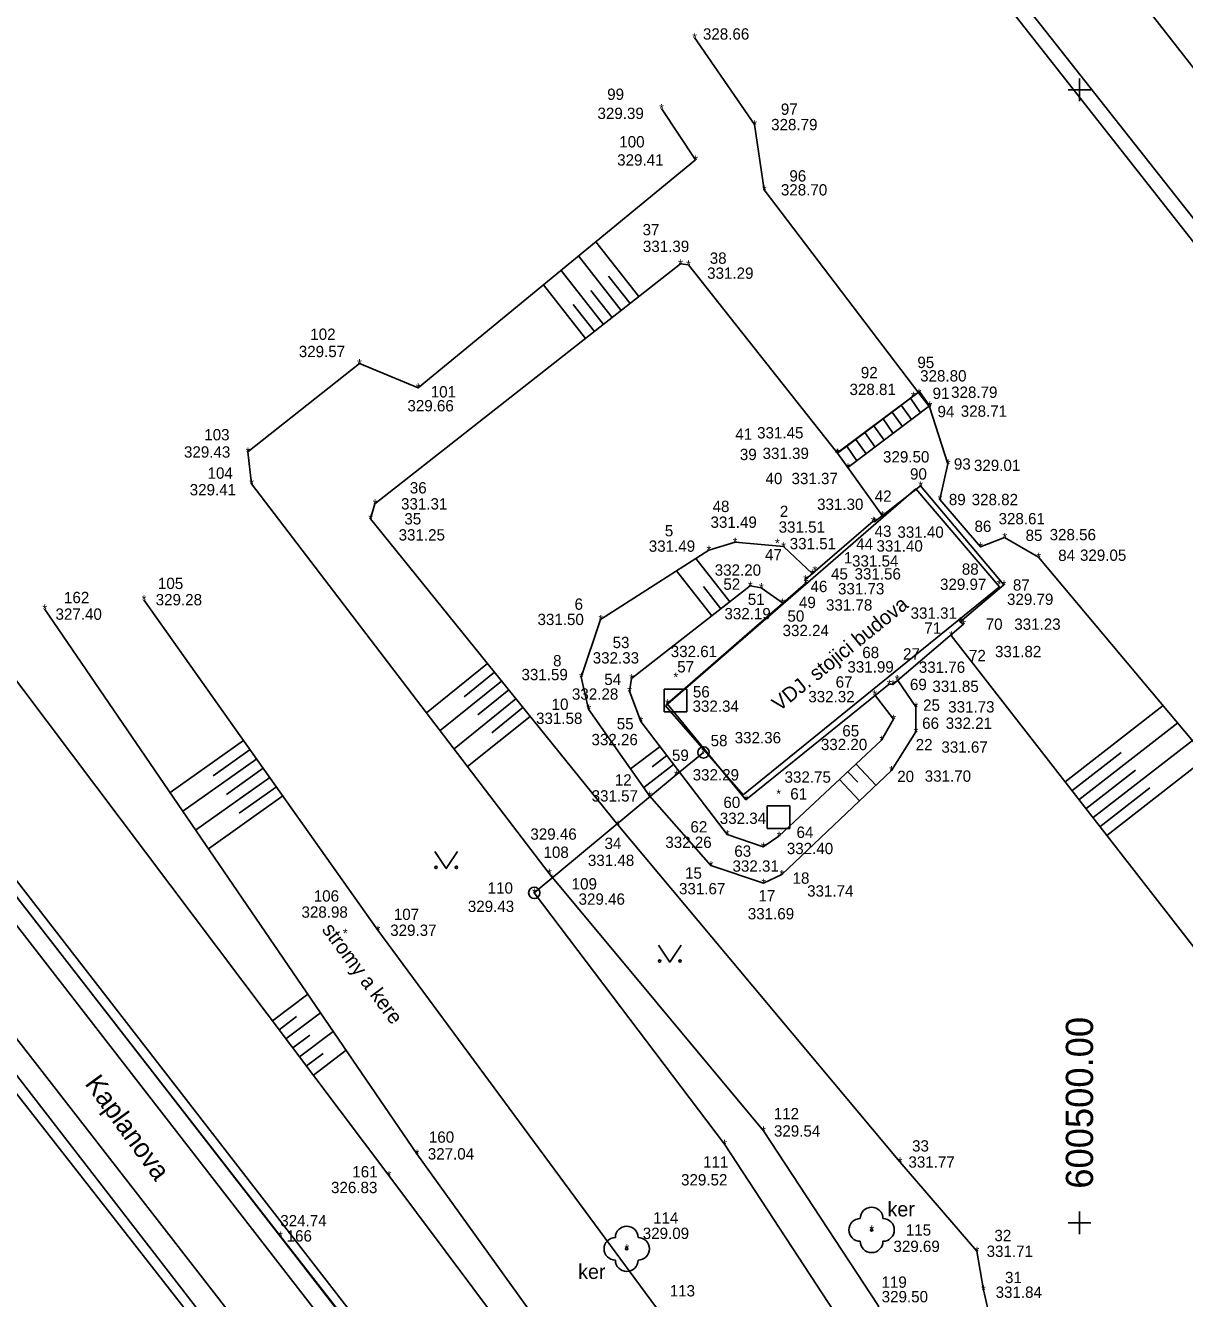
# Model space of a CAD drawing. Extents: x -600587 to -600377, y -1159886 to -1159708.
# Drawn here: x -600546.5 to -600495.4, y -1159803.3 to -1159747.2 of the extents above; entities that cross this region are included whole.
import ezdxf

# ---------------------------------------------------------------- set-up
doc = ezdxf.new("R2010")
doc.units = 0
for name, color, linetype in [('Hranice parcel', 7, 'Continuous'), ('Pop  PČ popisy', 7, 'Continuous'), ('Vnitřní kresba', 7, 'Continuous'), ('Vrstva 11', 7, 'Continuous'), ('Vrstva 13', 7, 'Continuous'), ('Vrstva 20', 7, 'Continuous'), ('Vrstva 22', 7, 'Continuous'), ('Vrstva 34', 7, 'Continuous'), ('Vrstva 36', 7, 'Continuous'), ('Vrstva 40', 7, 'Continuous'), ('Vrstva 58', 7, 'Continuous'), ('Vrstva 59', 7, 'Continuous'), ('Vrstva 60', 7, 'Continuous'), ('Vrstva 62', 7, 'Continuous'), ('Vrstva 63', 7, 'Continuous'), ('Vrstva 7', 7, 'Continuous'), ('Vrstva 8', 7, 'Continuous')]:
    doc.layers.add(name, color=color, linetype=linetype)

msp = doc.modelspace()

# ---------------------------------------------------------------- linework, layer by layer
at = {"layer": 'Hranice parcel'}
for points in [[(-600530.91, -1159710.13), (-600493.42, -1159757.63), (-600491.23, -1159760.48), (-600448.05, -1159816.59)], [(-600488.61, -1159847.98), (-600490.62, -1159848.62), (-600491.99, -1159848.82), (-600493.39, -1159848.77), (-600494.93, -1159848.62), (-600496.36, -1159848.13), (-600500.23, -1159845.75), (-600572.32, -1159752.89), (-600572.98, -1159751.48), (-600573.33, -1159750.24), (-600573.44, -1159748.95), (-600573.44, -1159747.6), (-600573.32, -1159746.25), (-600573.13, -1159744.93), (-600572.66, -1159743.72), (-600571.05, -1159741.4), (-600570.22, -1159740.33), (-600564.67, -1159736.09)], [(-600524.43, -1159822.45), (-600525.46, -1159821.09), (-600527.36, -1159818.8), (-600536.8, -1159806.55), (-600551.99, -1159786.94)]]:
    msp.add_lwpolyline(points, dxfattribs=at)
at = {"layer": 'Vnitřní kresba'}
for p, q in [((-600525.36, -1159709.98), (-600494.19, -1159750.03)), ((-600531.09, -1159710.8), (-600493.91, -1159758.06)), ((-600580.267, -1159748.971), (-600497.15, -1159855.9)), ((-600499.96, -1159845.44), (-600571.89, -1159752.7)), ((-600503.93, -1159842.26), (-600567.61, -1159760.2)), ((-600518.27, -1159777.18), (-600507.22, -1159767.61)), ((-600507.22, -1159767.61), (-600503.52, -1159771.93)), ((-600503.52, -1159771.93), (-600514.84, -1159781.11)), ((-600514.84, -1159781.11), (-600518.27, -1159777.18)), ((-600537.12, -1159806.8), (-600552.47, -1159787.22))]:
    msp.add_line(p, q, dxfattribs=at)
at = {"layer": 'Vrstva 11'}
for p, q in [((-600518.45, -1159750.82), (-600516.94, -1159753.09)), ((-600519.44, -1159759.12), (-600521.34, -1159756.7)), ((-600520.22, -1159759.73), (-600522.11, -1159757.33)), ((-600521.01, -1159760.35), (-600522.88, -1159757.97)), ((-600519.83, -1159759.42), (-600520.78, -1159758.22)), ((-600521.8, -1159760.97), (-600523.65, -1159758.6)), ((-600520.62, -1159760.04), (-600521.56, -1159758.85)), ((-600521.4, -1159760.66), (-600522.34, -1159759.47)), ((-600507.412, -1159764.554), (-600507.862, -1159763.914)), ((-600507.011, -1159764.252), (-600507.461, -1159763.612)), ((-600508.214, -1159765.159), (-600508.664, -1159764.519)), ((-600507.813, -1159764.857), (-600508.263, -1159764.217)), ((-600509.017, -1159765.763), (-600509.467, -1159765.123)), ((-600508.616, -1159765.461), (-600509.066, -1159764.821)), ((-600509.418, -1159766.066), (-600509.868, -1159765.426)), ((-600509.819, -1159766.368), (-600510.269, -1159765.728)), ((-600515.43, -1159772.59), (-600516.93, -1159770.68)), ((-600516.22, -1159773.21), (-600517.78, -1159771.22)), ((-600515.83, -1159772.9), (-600516.59, -1159771.92)), ((-600526.13, -1159775.31), (-600528.82, -1159777.49)), ((-600525.82, -1159775.7), (-600527.16, -1159776.79)), ((-600525.5, -1159776.09), (-600528.21, -1159778.28)), ((-600524.87, -1159776.87), (-600527.6, -1159779.08)), ((-600525.19, -1159776.48), (-600526.55, -1159777.58)), ((-600524.56, -1159777.26), (-600525.93, -1159778.37)), ((-600500.63, -1159780.54), (-600496.3, -1159777.17)), ((-600524.24, -1159777.65), (-600527, -1159779.87)), ((-600500.02, -1159781.33), (-600495.66, -1159777.94)), ((-600536.89, -1159778.72), (-600540.13, -1159781.01)), ((-600536.6, -1159779.12), (-600538.23, -1159780.28)), ((-600518.51, -1159778.98), (-600519.81, -1159779.97)), ((-600499.4, -1159782.12), (-600495.01, -1159778.71)), ((-600536.31, -1159779.53), (-600539.57, -1159781.84)), ((-600518.21, -1159779.38), (-600518.86, -1159779.88)), ((-600500.33, -1159780.94), (-600498.15, -1159779.25)), ((-600498.79, -1159782.91), (-600494.37, -1159779.47)), ((-600536.02, -1159779.94), (-600537.65, -1159781.1)), ((-600517.91, -1159779.77), (-600519.23, -1159780.79)), ((-600510.22, -1159780.1), (-600509.78, -1159780.56)), ((-600509.86, -1159779.76), (-600508.98, -1159780.69)), ((-600499.71, -1159781.73), (-600497.52, -1159780.03)), ((-600535.73, -1159780.35), (-600539.01, -1159782.67)), ((-600535.44, -1159780.76), (-600537.08, -1159781.92)), ((-600510.59, -1159780.44), (-600509.71, -1159781.38)), ((-600499.1, -1159782.52), (-600496.89, -1159780.8)), ((-600535.16, -1159781.16), (-600538.44, -1159783.49)), ((-600535.62, -1159791.09), (-600534.06, -1159789.91)), ((-600535.32, -1159791.49), (-600534.55, -1159790.9)), ((-600535.02, -1159791.88), (-600533.49, -1159790.74)), ((-600534.72, -1159792.28), (-600533.96, -1159791.72)), ((-600534.42, -1159792.68), (-600532.93, -1159791.56)), ((-600534.11, -1159793.08), (-600533.38, -1159792.53)), ((-600533.81, -1159793.48), (-600532.36, -1159792.39))]:
    msp.add_line(p, q, dxfattribs=at)
for points in [[(-600505.8, -1159766.51), (-600506.62, -1159763.99), (-600507.09, -1159763.39), (-600513.91, -1159754.41), (-600514.34, -1159751.53), (-600516.99, -1159747.69)], [(-600516.94, -1159753.09), (-600529.19, -1159763.15), (-600531.78, -1159762.08), (-600536.7, -1159765.98), (-600536.54, -1159767.38), (-600523.4, -1159784.58), (-600513.95, -1159795.95), (-600508.88, -1159803.66), (-600507.89, -1159806.61), (-600497.07, -1159821.79)], [(-600484.2, -1159818.25), (-600488.9, -1159822.049), (-600490.752, -1159822.336), (-600491.864, -1159821.583), (-600494.57, -1159818.11), (-600499.67, -1159810.97), (-600503.93, -1159804.31), (-600504.24, -1159802.96), (-600504.53, -1159801.26), (-600507.92, -1159797.32), (-600520.37, -1159782.44), (-600531.29, -1159768.93), (-600531.09, -1159768.27), (-600517.61, -1159757.68), (-600517.26, -1159757.72), (-600510.67, -1159766.03), (-600510.22, -1159766.67), (-600508.71, -1159768.78)], [(-600510.67, -1159766.03), (-600507.06, -1159763.31), (-600506.61, -1159763.95)], [(-600510.67, -1159766.03), (-600510.22, -1159766.67), (-600506.61, -1159763.95)], [(-600502.72, -1159834.41), (-600509.56, -1159825.58), (-600519.31, -1159812.85), (-600530.48, -1159797.91), (-600554.16, -1159766.46)], [(-600473.743, -1159793.926), (-600480.83, -1159785.76), (-600491.06, -1159783.42), (-600501.8, -1159770.62), (-600503.3, -1159769.75), (-600504.37, -1159770.17), (-600506.16, -1159768.08), (-600505.8, -1159766.51)], [(-600511.78, -1159771.36), (-600513.06, -1159770.16), (-600515.2, -1159769.96), (-600516.36, -1159770.31), (-600521.13, -1159773.37), (-600521.99, -1159775.92), (-600521.66, -1159777.33), (-600518.97, -1159781.16), (-600516.27, -1159784.24), (-600513.94, -1159785.01), (-600513.14, -1159784.63), (-600508.3, -1159780.04), (-600507.22, -1159778.34), (-600507.22, -1159777.23), (-600508.05, -1159776.03)], [(-600513.1, -1159772.64), (-600514.04, -1159771.97), (-600514.53, -1159771.89), (-600519.77, -1159775.98), (-600519.86, -1159776.54), (-600519.36, -1159777.87), (-600515.55, -1159782.86), (-600513.96, -1159783.41), (-600513.26, -1159782.94), (-600508.73, -1159778.7), (-600508.2, -1159777.77), (-600509.04, -1159776.69)], [(-600508.65, -1159825.2), (-600518.33, -1159812.15), (-600529.24, -1159796.96), (-600545.67, -1159772.91)], [(-600541.29, -1159772.5), (-600530.96, -1159787.09), (-600518.71, -1159803.7), (-600511.21, -1159813.31), (-600502.87, -1159824.07)], [(-600505.66, -1159774.08), (-600492.78, -1159790.64), (-600491.93, -1159791.2), (-600487.96, -1159791.96), (-600485.28, -1159791.6), (-600484.47, -1159791.86), (-600480.26, -1159798.5)]]:
    msp.add_lwpolyline(points, dxfattribs=at)
at = {"layer": 'Vrstva 13'}
msp.add_lwpolyline([(-600497.65, -1159824.35), (-600503.84, -1159814.83), (-600509.44, -1159806.04), (-600515.67, -1159796.54), (-600524.06, -1159785.44), (-600517.8, -1159780.23), (-600516.59, -1159779.24)], dxfattribs=at)
at = {"layer": 'Vrstva 20'}
msp.add_lwpolyline([(-600509.05, -1159769.06), (-600509.1, -1159769.04), (-600512.09, -1159771.61), (-600512.08, -1159771.77), (-600518.19, -1159777.09), (-600514.72, -1159781.33), (-600508.4, -1159776.23), (-600508.23, -1159776.24), (-600505.12, -1159773.58), (-600505.27, -1159773.48), (-600503.34, -1159771.85), (-600507.01, -1159767.47)], close=True, dxfattribs=at)
at = {"layer": 'Vrstva 22'}
for centre in [(-600509.17, -1159800.32), (-600519.98, -1159801.15)]:
    msp.add_circle(centre, 0.05, dxfattribs=at)
for centre, start, end in [((-600509.17, -1159799.82), 0, 180), ((-600509.67, -1159800.32), 90, 270), ((-600508.67, -1159800.32), 270, 90), ((-600519.98, -1159800.65), 0, 180), ((-600520.48, -1159801.15), 90, 270), ((-600519.48, -1159801.15), 270, 90), ((-600509.17, -1159800.82), 180, 0), ((-600519.98, -1159801.65), 180, 0)]:
    msp.add_arc(centre, 0.5, start, end, dxfattribs=at)
at = {"layer": 'Vrstva 34'}
for p, q in [((-600517.32, -1159776.45), (-600518.32, -1159776.45)), ((-600518.32, -1159776.45), (-600518.32, -1159777.45)), ((-600517.32, -1159777.45), (-600517.32, -1159776.45)), ((-600518.32, -1159777.45), (-600517.32, -1159777.45)), ((-600512.78, -1159781.6), (-600513.78, -1159781.6)), ((-600513.78, -1159781.6), (-600513.78, -1159782.6)), ((-600512.78, -1159782.6), (-600512.78, -1159781.6)), ((-600513.78, -1159782.6), (-600512.78, -1159782.6))]:
    msp.add_line(p, q, dxfattribs=at)
at = {"layer": 'Vrstva 36'}
for points in [[(-600528.446, -1159783.616), (-600527.946, -1159784.366), (-600527.446, -1159783.616)], [(-600518.577, -1159787.749), (-600518.077, -1159788.499), (-600517.577, -1159787.749)]]:
    msp.add_lwpolyline(points, dxfattribs=at)
for centre in [(-600528.397, -1159784.316), (-600527.497, -1159784.316), (-600518.527, -1159788.449), (-600517.628, -1159788.449)]:
    msp.add_circle(centre, 0.05, dxfattribs=at)
at = {"layer": 'Vrstva 63'}
for p, q in [((-600500, -1159749.5), (-600500, -1159750.5)), ((-600500.5, -1159750), (-600499.5, -1159750)), ((-600500, -1159799.5), (-600500, -1159800.5)), ((-600500.5, -1159800), (-600499.5, -1159800))]:
    msp.add_line(p, q, dxfattribs=at)
at = {"layer": 'Vrstva 7'}
msp.add_lwpolyline([(-600566.21, -1159760.89), (-600549.54, -1159782.24), (-600535.27, -1159800.58), (-600519.17, -1159821.21), (-600501, -1159844.58)], dxfattribs=at)
at = {"layer": 'Vrstva 8'}
msp.add_lwpolyline([(-600510.71, -1159766.04), (-600507.34, -1159763.52)], dxfattribs=at)
for centre, radius in [((-600516.591, -1159779.24), 0.25), ((-600516.591, -1159779.24), 0.0005), ((-600524.061, -1159785.44), 0.25), ((-600524.061, -1159785.44), 0.0005)]:
    msp.add_circle(centre, radius, dxfattribs=at)

# ---------------------------------------------------------------- texts
at = {"layer": 'Pop  PČ popisy'}
msp.add_text('Kaplanova', height=0.85, rotation=306, dxfattribs=at).set_placement((-600543.924, -1159793.865))
at = {"layer": 'Vrstva 40'}
for s, rotation, p in [('VDJ. stojici budova', 38.9022, (-600513.248, -1159777.453)), ('stromy a kere', 306.4091, (-600533.463, -1159787.069))]:
    msp.add_text(s, height=0.65, rotation=rotation, dxfattribs=at).set_placement(p)
for p in [(-600508.471, -1159799.724), (-600522.124, -1159802.483)]:
    msp.add_text('ker', height=0.65, dxfattribs=at).set_placement(p)
at = {"layer": 'Vrstva 58'}
for s, p in [('328.66', (-600516.616, -1159747.78)), ('329.39', (-600521.27, -1159751.284)), ('328.79', (-600513.605, -1159751.78)), ('329.41', (-600520.401, -1159753.34)), ('328.70', (-600513.175, -1159754.66)), ('331.39', (-600519.267, -1159757.153)), ('331.29', (-600516.431, -1159758.338)), ('329.57', (-600534.453, -1159761.795)), ('328.80', (-600507.029, -1159762.87)), ('328.81', (-600510.146, -1159763.468)), ('328.79', (-600505.663, -1159763.593)), ('329.66', (-600529.658, -1159764.189)), ('328.71', (-600505.237, -1159764.427)), ('331.45', (-600514.225, -1159765.384)), ('329.43', (-600539.52, -1159766.23)), ('331.39', (-600513.984, -1159766.29)), ('329.50', (-600508.667, -1159766.444)), ('329.01', (-600504.655, -1159766.821)), ('331.37', (-600512.706, -1159767.401)), ('329.41', (-600539.266, -1159767.897)), ('328.82', (-600504.755, -1159768.33)), ('331.31', (-600529.941, -1159768.52)), ('331.30', (-600511.577, -1159768.539)), ('331.49', (-600516.282, -1159769.329)), ('331.51', (-600513.275, -1159769.544)), ('328.61', (-600503.568, -1159769.174)), ('331.25', (-600530.047, -1159769.889)), ('331.40', (-600508.032, -1159769.767)), ('328.56', (-600501.315, -1159769.878)), ('331.49', (-600519.006, -1159770.386)), ('331.51', (-600512.785, -1159770.275)), ('331.40', (-600508.957, -1159770.378)), ('331.54', (-600510.034, -1159771.04)), ('329.05', (-600499.975, -1159770.786)), ('332.20', (-600516.095, -1159771.442)), ('331.56', (-600509.924, -1159771.61)), ('331.73', (-600510.654, -1159772.267)), ('329.97', (-600506.152, -1159772.07)), ('329.28', (-600540.769, -1159772.75)), ('329.79', (-600503.195, -1159772.732)), ('327.40', (-600545.189, -1159773.387)), ('332.19', (-600515.667, -1159773.367)), ('331.78', (-600511.185, -1159772.983)), ('331.31', (-600507.451, -1159773.341)), ('331.50', (-600523.917, -1159773.62)), ('331.23', (-600502.875, -1159773.83)), ('332.24', (-600513.1, -1159774.109)), ('332.61', (-600518.036, -1159775.035)), ('331.82', (-600503.728, -1159775.04)), ('332.33', (-600521.48, -1159775.318)), ('331.99', (-600510.24, -1159775.716)), ('331.76', (-600507.088, -1159775.73)), ('331.59', (-600524.624, -1159776.055)), ('331.85', (-600506.489, -1159776.572)), ('332.28', (-600522.397, -1159776.915)), ('332.32', (-600511.965, -1159777.03)), ('331.58', (-600523.981, -1159777.985)), ('332.34', (-600517.074, -1159777.45)), ('331.73', (-600505.792, -1159777.48)), ('332.21', (-600505.902, -1159778.203)), ('332.26', (-600521.534, -1159778.925)), ('332.36', (-600515.214, -1159778.84)), ('332.20', (-600511.41, -1159779.14)), ('331.67', (-600506.09, -1159779.255)), ('332.29', (-600517.069, -1159780.48)), ('332.75', (-600513.013, -1159780.579)), ('331.70', (-600506.826, -1159780.535)), ('331.57', (-600521.528, -1159781.41)), ('332.34', (-600515.873, -1159782.398)), ('329.46', (-600524.232, -1159783.095)), ('332.26', (-600518.276, -1159783.458)), ('332.40', (-600512.913, -1159783.731)), ('331.48', (-600521.693, -1159784.255)), ('332.31', (-600515.31, -1159784.507)), ('331.67', (-600517.673, -1159785.506)), ('331.74', (-600512.017, -1159785.605)), ('329.43', (-600526.992, -1159786.286)), ('329.46', (-600522.104, -1159785.965)), ('328.98', (-600534.334, -1159786.538)), ('331.69', (-600514.635, -1159786.611)), ('329.37', (-600530.418, -1159787.34)), ('329.54', (-600513.482, -1159796.2)), ('327.04', (-600528.759, -1159797.21)), ('331.77', (-600507.546, -1159797.57)), ('326.83', (-600533.03, -1159798.695)), ('329.52', (-600517.581, -1159798.355)), ('324.74', (-600535.27, -1159800.161)), ('329.09', (-600519.272, -1159800.718)), ('329.69', (-600508.208, -1159801.292)), ('331.71', (-600504.095, -1159801.51)), ('329.50', (-600508.727, -1159803.513)), ('331.84', (-600503.698, -1159803.317))]:
    msp.add_text(s, height=0.5, dxfattribs=at).set_placement(p)
at = {"layer": 'Vrstva 59'}
for s, p in [('99', (-600520.842, -1159750.441)), ('97', (-600513.177, -1159751.098)), ('100', (-600520.308, -1159752.538)), ('96', (-600512.801, -1159754.045)), ('37', (-600519.28, -1159756.417)), ('38', (-600516.315, -1159757.676)), ('102', (-600533.946, -1159761.033)), ('92', (-600509.648, -1159762.726)), ('95', (-600507.151, -1159762.277)), ('101', (-600528.629, -1159763.574)), ('91', (-600506.479, -1159763.641)), ('94', (-600506.263, -1159764.446)), ('103', (-600538.624, -1159765.468)), ('41', (-600515.187, -1159765.443)), ('39', (-600514.986, -1159766.339)), ('93', (-600505.54, -1159766.76)), ('104', (-600538.478, -1159767.162)), ('90', (-600507.476, -1159767.2)), ('36', (-600529.553, -1159767.811)), ('40', (-600513.855, -1159767.401)), ('42', (-600509.034, -1159768.179)), ('89', (-600505.763, -1159768.33)), ('48', (-600516.189, -1159768.633)), ('2', (-600513.222, -1159768.85)), ('35', (-600529.793, -1159769.18)), ('86', (-600504.63, -1159769.511)), ('5', (-600518.298, -1159769.703)), ('43', (-600509.039, -1159769.728)), ('85', (-600502.376, -1159769.908)), ('44', (-600509.852, -1159770.287)), ('47', (-600513.876, -1159770.768)), ('1', (-600510.397, -1159770.902)), ('84', (-600500.937, -1159770.794)), ('45', (-600510.963, -1159771.61)), ('88', (-600505.19, -1159771.4)), ('105', (-600540.668, -1159772.03)), ('52', (-600515.714, -1159772.064)), ('46', (-600511.869, -1159772.166)), ('87', (-600502.935, -1159772.1)), ('162', (-600544.815, -1159772.654)), ('51', (-600514.636, -1159772.732)), ('49', (-600512.378, -1159772.871)), ('6', (-600522.282, -1159772.947)), ('50', (-600512.886, -1159773.471)), ('71', (-600506.847, -1159774.006)), ('70', (-600504.135, -1159773.83)), ('53', (-600520.602, -1159774.638)), ('68', (-600509.583, -1159775.081)), ('27', (-600507.783, -1159775.143)), ('8', (-600523.229, -1159775.444)), ('57', (-600517.751, -1159775.711)), ('72', (-600504.873, -1159775.216)), ('54', (-600520.969, -1159776.265)), ('56', (-600517.059, -1159776.816)), ('67', (-600510.758, -1159776.381)), ('69', (-600507.48, -1159776.49)), ('10', (-600523.294, -1159777.366)), ('25', (-600506.899, -1159777.404)), ('55', (-600520.419, -1159778.222)), ('65', (-600510.463, -1159778.537)), ('66', (-600506.94, -1159778.203)), ('58', (-600516.276, -1159778.968)), ('59', (-600517.983, -1159779.616)), ('22', (-600507.225, -1159779.148)), ('12', (-600520.505, -1159780.707)), ('20', (-600508.04, -1159780.55)), ('61', (-600512.761, -1159781.32)), ('60', (-600515.713, -1159781.695)), ('62', (-600517.167, -1159782.776)), ('64', (-600512.485, -1159783.016)), ('34', (-600520.958, -1159783.506)), ('108', (-600523.652, -1159783.898)), ('63', (-600515.23, -1159783.847)), ('109', (-600522.409, -1159785.292)), ('15', (-600517.406, -1159784.816)), ('18', (-600512.659, -1159785.04)), ('106', (-600533.792, -1159785.827)), ('110', (-600526.117, -1159785.476)), ('17', (-600514.167, -1159785.819)), ('107', (-600530.257, -1159786.637)), ('112', (-600513.491, -1159795.438)), ('160', (-600528.711, -1159796.469)), ('33', (-600507.385, -1159796.859)), ('111', (-600516.609, -1159797.566)), ('161', (-600532.091, -1159798)), ('114', (-600518.817, -1159800.036)), ('166', (-600534.989, -1159800.83)), ('115', (-600507.66, -1159800.57)), ('32', (-600503.751, -1159800.815)), ('31', (-600503.285, -1159802.667)), ('113', (-600518.082, -1159803.255)), ('119', (-600508.735, -1159802.871))]:
    msp.add_text(s, height=0.5, dxfattribs=at).set_placement(p)
at = {"layer": 'Vrstva 60'}
for p in [(-600517.088, -1159747.89), (-600518.548, -1159751.02), (-600514.438, -1159751.73), (-600517.038, -1159753.29), (-600514.008, -1159754.61), (-600517.708, -1159757.88), (-600517.358, -1159757.92), (-600531.878, -1159762.28), (-600529.288, -1159763.35), (-600507.438, -1159763.72), (-600507.188, -1159763.59), (-600506.718, -1159764.19), (-600506.708, -1159764.15), (-600536.798, -1159766.18), (-600510.808, -1159766.24), (-600510.768, -1159766.23), (-600510.318, -1159766.87), (-600505.898, -1159766.71), (-600536.638, -1159767.58), (-600507.108, -1159767.67), (-600506.258, -1159768.28), (-600531.188, -1159768.47), (-600531.388, -1159769.13), (-600509.198, -1159769.24), (-600509.148, -1159769.26), (-600508.808, -1159768.98), (-600503.398, -1159769.95), (-600516.458, -1159770.51), (-600515.298, -1159770.16), (-600513.438, -1159770.21), (-600513.158, -1159770.36), (-600504.468, -1159770.37), (-600501.898, -1159770.82), (-600511.878, -1159771.56), (-600511.778, -1159771.41), (-600514.628, -1159772.09), (-600514.138, -1159772.17), (-600512.188, -1159771.81), (-600512.178, -1159771.97), (-600503.658, -1159772.02), (-600503.438, -1159772.05), (-600541.388, -1159772.7), (-600545.768, -1159773.11), (-600513.198, -1159772.84), (-600521.228, -1159773.57), (-600505.368, -1159773.68), (-600505.218, -1159773.78), (-600505.758, -1159774.28), (-600522.088, -1159776.12), (-600519.868, -1159776.18), (-600517.918, -1159776.12), (-600519.958, -1159776.74), (-600508.498, -1159776.43), (-600508.328, -1159776.44), (-600508.148, -1159776.23), (-600518.288, -1159777.29), (-600509.138, -1159776.89), (-600521.758, -1159777.53), (-600507.318, -1159777.43), (-600519.458, -1159778.07), (-600508.298, -1159777.97), (-600508.828, -1159778.9), (-600507.318, -1159778.54), (-600516.688, -1159779.44), (-600517.898, -1159780.43), (-600508.398, -1159780.24), (-600519.068, -1159781.36), (-600514.818, -1159781.53), (-600513.378, -1159781.27), (-600520.468, -1159782.64), (-600515.648, -1159783.06), (-600513.358, -1159783.14), (-600514.058, -1159783.61), (-600516.368, -1159784.44), (-600523.498, -1159784.78), (-600523.378, -1159785.02), (-600513.238, -1159784.83), (-600524.158, -1159785.64), (-600514.038, -1159785.21), (-600532.508, -1159787.42), (-600531.058, -1159787.29), (-600514.048, -1159796.15), (-600515.768, -1159796.74), (-600529.338, -1159797.16), (-600508.018, -1159797.52), (-600530.578, -1159798.11), (-600535.368, -1159800.78), (-600509.268, -1159800.52), (-600520.078, -1159801.35), (-600504.628, -1159801.46), (-600504.338, -1159803.16)]:
    msp.add_text('*', height=0.4, dxfattribs=at).set_placement(p)
at = {"layer": 'Vrstva 62'}
msp.add_text('600500.00', height=1.2, rotation=90, dxfattribs=at).set_placement((-600499.4, -1159798.5))

doc.saveas('drawing.dxf')
